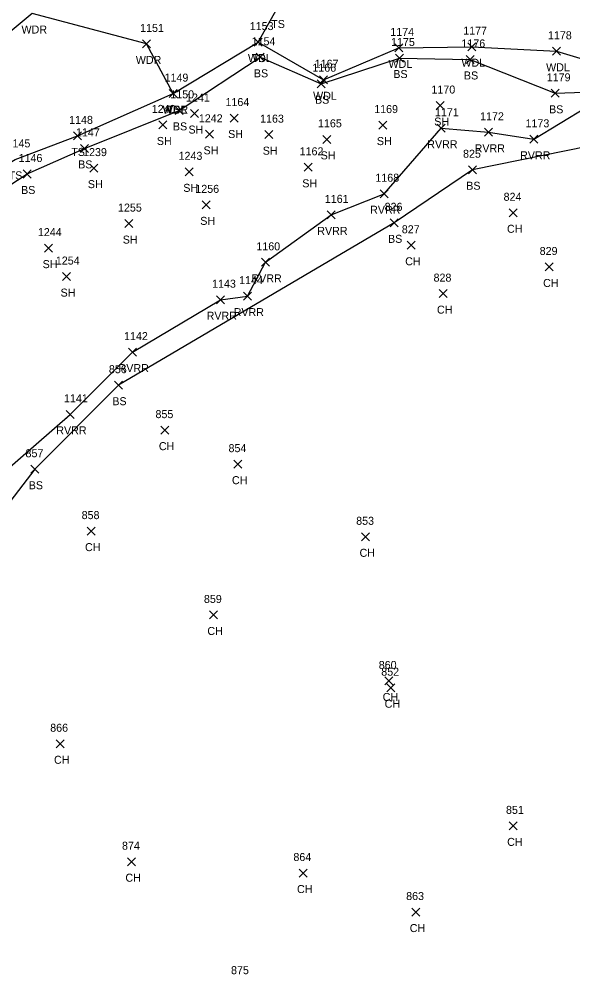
# Model space of a CAD drawing. Extents: x 1885914 to 1887218, y 756253 to 760620.
# Drawn here: x 1886700.7 to 1886839.1, y 759954.5 to 760195 of the extents above; entities that cross this region are included whole.
import ezdxf

# ---------------------------------------------------------------- set-up
doc = ezdxf.new("R2010")
doc.units = 0
for name, color, linetype in [('L_A', 7, 'Continuous'), ('L_I', 7, 'Continuous'), ('L_TIC', 7, 'Continuous'), ('LAWA', 7, 'Continuous'), ('LAWE', 7, 'Continuous'), ('LELB', 7, 'Continuous')]:
    doc.layers.add(name, color=color, linetype=linetype)

msp = doc.modelspace()

# ---------------------------------------------------------------- linework, layer by layer
at = {"layer": 'L_TIC'}
for points in [[(1886759.47, 760188.26), (1886761.47, 760190.26)], [(1886761.47, 760188.26), (1886759.47, 760190.26)], [(1886759.47, 760188.26), (1886761.47, 760190.26)], [(1886761.47, 760188.26), (1886759.47, 760190.26)], [(1886731.49, 760187.8), (1886733.49, 760189.8)], [(1886733.49, 760187.8), (1886731.49, 760189.8)], [(1886794.61, 760186.81), (1886796.61, 760188.81)], [(1886796.61, 760186.81), (1886794.61, 760188.81)], [(1886812.83, 760187.11), (1886814.83, 760189.11)], [(1886814.83, 760187.11), (1886812.83, 760189.11)], [(1886834.01, 760185.96), (1886836.01, 760187.96)], [(1886836.01, 760185.96), (1886834.01, 760187.96)], [(1886759.93, 760184.46), (1886761.93, 760186.46)], [(1886761.93, 760184.46), (1886759.93, 760186.46)], [(1886794.79, 760184.28), (1886796.79, 760186.28)], [(1886796.79, 760184.28), (1886794.79, 760186.28)], [(1886812.44, 760183.92), (1886814.44, 760185.92)], [(1886814.44, 760183.92), (1886812.44, 760185.92)], [(1886775.75, 760178.85), (1886777.75, 760180.85)], [(1886777.75, 760178.85), (1886775.75, 760180.85)], [(1886775.22, 760177.86), (1886777.22, 760179.86)], [(1886777.22, 760177.86), (1886775.22, 760179.86)], [(1886738.18, 760175.38), (1886740.18, 760177.38)], [(1886740.18, 760175.38), (1886738.18, 760177.38)], [(1886738.18, 760175.38), (1886740.18, 760177.38)], [(1886740.18, 760175.38), (1886738.18, 760177.38)], [(1886738.18, 760175.38), (1886740.18, 760177.38)], [(1886740.18, 760175.38), (1886738.18, 760177.38)], [(1886833.73, 760175.46), (1886835.73, 760177.46)], [(1886835.73, 760175.46), (1886833.73, 760177.46)], [(1886804.97, 760172.4), (1886806.97, 760174.4)], [(1886806.97, 760172.4), (1886804.97, 760174.4)], [(1886739.68, 760171.2), (1886741.68, 760173.2)], [(1886741.68, 760171.2), (1886739.68, 760173.2)], [(1886743.53, 760170.4), (1886745.53, 760172.4)], [(1886745.53, 760170.4), (1886743.53, 760172.4)], [(1886753.45, 760169.28), (1886755.45, 760171.28)], [(1886755.45, 760169.28), (1886753.45, 760171.28)], [(1886735.62, 760167.56), (1886737.62, 760169.56)], [(1886737.62, 760167.56), (1886735.62, 760169.56)], [(1886790.63, 760167.52), (1886792.63, 760169.52)], [(1886792.63, 760167.52), (1886790.63, 760169.52)], [(1886805.2, 760166.73), (1886807.2, 760168.73)], [(1886807.2, 760166.73), (1886805.2, 760168.73)], [(1886714.31, 760164.82), (1886716.31, 760166.82)], [(1886716.31, 760164.82), (1886714.31, 760166.82)], [(1886747.3, 760165.22), (1886749.3, 760167.22)], [(1886749.3, 760165.22), (1886747.3, 760167.22)], [(1886762.1, 760165.13), (1886764.1, 760167.13)], [(1886764.1, 760165.13), (1886762.1, 760167.13)], [(1886817.04, 760165.72), (1886819.04, 760167.72)], [(1886819.04, 760165.72), (1886817.04, 760167.72)], [(1886776.57, 760163.96), (1886778.57, 760165.96)], [(1886778.57, 760163.96), (1886776.57, 760165.96)], [(1886828.4, 760163.97), (1886830.4, 760165.97)], [(1886830.4, 760163.97), (1886828.4, 760165.97)], [(1886716, 760161.7), (1886718, 760163.7)], [(1886718, 760161.7), (1886716, 760163.7)], [(1886771.98, 760156.97), (1886773.98, 760158.97)], [(1886773.98, 760156.97), (1886771.98, 760158.97)], [(1886701.73, 760155.3), (1886703.73, 760157.3)], [(1886703.73, 760155.3), (1886701.73, 760157.3)], [(1886718.37, 760156.77), (1886720.37, 760158.77)], [(1886720.37, 760156.77), (1886718.37, 760158.77)], [(1886742.23, 760155.84), (1886744.23, 760157.84)], [(1886744.23, 760155.84), (1886742.23, 760157.84)], [(1886813.02, 760156.37), (1886815.02, 760158.37)], [(1886815.02, 760156.37), (1886813.02, 760158.37)], [(1886790.91, 760150.37), (1886792.91, 760152.37)], [(1886792.91, 760150.37), (1886790.91, 760152.37)], [(1886746.48, 760147.59), (1886748.48, 760149.59)], [(1886748.48, 760147.59), (1886746.48, 760149.59)], [(1886777.71, 760145.09), (1886779.71, 760147.09)], [(1886779.71, 760145.09), (1886777.71, 760147.09)], [(1886823.16, 760145.61), (1886825.16, 760147.61)], [(1886825.16, 760145.61), (1886823.16, 760147.61)], [(1886727.09, 760142.91), (1886729.09, 760144.91)], [(1886729.09, 760142.91), (1886727.09, 760144.91)], [(1886793.47, 760143.1), (1886795.47, 760145.1)], [(1886795.47, 760143.1), (1886793.47, 760145.1)], [(1886707.06, 760136.78), (1886709.06, 760138.78)], [(1886709.06, 760136.78), (1886707.06, 760138.78)], [(1886797.71, 760137.49), (1886799.71, 760139.49)], [(1886799.71, 760137.49), (1886797.71, 760139.49)], [(1886761.25, 760133.23), (1886763.25, 760135.23)], [(1886763.25, 760133.23), (1886761.25, 760135.23)], [(1886832.19, 760132.07), (1886834.19, 760134.07)], [(1886834.19, 760132.07), (1886832.19, 760134.07)], [(1886711.56, 760129.67), (1886713.56, 760131.67)], [(1886713.56, 760129.67), (1886711.56, 760131.67)], [(1886750.04, 760123.89), (1886752.04, 760125.89)], [(1886752.04, 760123.89), (1886750.04, 760125.89)], [(1886756.81, 760124.78), (1886758.81, 760126.78)], [(1886758.81, 760124.78), (1886756.81, 760126.78)], [(1886805.66, 760125.41), (1886807.66, 760127.41)], [(1886807.66, 760125.41), (1886805.66, 760127.41)], [(1886728.03, 760110.8), (1886730.03, 760112.8)], [(1886730.03, 760110.8), (1886728.03, 760112.8)], [(1886724.54, 760102.53), (1886726.54, 760104.53)], [(1886726.54, 760102.53), (1886724.54, 760104.53)], [(1886712.46, 760095.25), (1886714.46, 760097.25)], [(1886714.46, 760095.25), (1886712.46, 760097.25)], [(1886736.13, 760091.3), (1886738.13, 760093.3)], [(1886738.13, 760091.3), (1886736.13, 760093.3)], [(1886754.39, 760082.8), (1886756.39, 760084.8)], [(1886756.39, 760082.8), (1886754.39, 760084.8)], [(1886703.64, 760081.53), (1886705.64, 760083.53)], [(1886705.64, 760081.53), (1886703.64, 760083.53)], [(1886717.67, 760066.07), (1886719.67, 760068.07)], [(1886719.67, 760066.07), (1886717.67, 760068.07)], [(1886786.31, 760064.65), (1886788.31, 760066.65)], [(1886788.31, 760064.65), (1886786.31, 760066.65)], [(1886748.25, 760045.12), (1886750.25, 760047.12)], [(1886750.25, 760045.12), (1886748.25, 760047.12)], [(1886792.08, 760028.63), (1886794.08, 760030.63)], [(1886794.08, 760028.63), (1886792.08, 760030.63)], [(1886792.57, 760026.94), (1886794.57, 760028.94)], [(1886794.57, 760026.94), (1886792.57, 760028.94)], [(1886709.91, 760012.94), (1886711.91, 760014.94)], [(1886711.91, 760012.94), (1886709.91, 760014.94)], [(1886823.2, 759992.42), (1886825.2, 759994.42)], [(1886825.2, 759992.42), (1886823.2, 759994.42)], [(1886727.76, 759983.47), (1886729.76, 759985.47)], [(1886729.76, 759983.47), (1886727.76, 759985.47)], [(1886770.66, 759980.64), (1886772.66, 759982.64)], [(1886772.66, 759980.64), (1886770.66, 759982.64)], [(1886798.85, 759970.89), (1886800.85, 759972.89)], [(1886800.85, 759970.89), (1886798.85, 759972.89)]]:
    msp.add_lwpolyline(points, dxfattribs=at)
at = {"layer": 'LAWA'}
for points in [[(1886739.18, 760176.38), (1886732.49, 760188.8), (1886703.91, 760196.4), (1886681.18, 760177.48), (1886662.74, 760171.57), (1886662.99, 760182.72), (1886681.62, 760215.3), (1886695.77, 760245.06), (1886708.75, 760275.76), (1886734.57, 760330.32)], [(1886739.18, 760176.38), (1886760.47, 760189.26), (1886776.75, 760179.85), (1886795.61, 760187.81), (1886813.83, 760188.11), (1886835.01, 760186.96), (1886850.86, 760182.23), (1886861.69, 760175.78)]]:
    msp.add_lwpolyline(points, dxfattribs=at)
at = {"layer": 'LAWE'}
msp.add_lwpolyline([(1886643.57, 759950.66), (1886647.93, 759967.68), (1886650.25, 759980.54), (1886657.27, 760004.64), (1886666.09, 760031.44), (1886675.36, 760057.62), (1886682.23, 760063.3), (1886696.4, 760081.41), (1886713.46, 760096.25), (1886729.03, 760111.8), (1886751.04, 760124.89), (1886757.81, 760125.78), (1886762.25, 760134.23), (1886778.71, 760146.09), (1886791.91, 760151.37), (1886806.2, 760167.73), (1886818.04, 760166.72), (1886829.4, 760164.97), (1886849.11, 760176.99)], dxfattribs=at)
at = {"layer": 'LELB'}
for points in [[(1886760.47, 760189.26), (1886765.29, 760197.79), (1886777.79, 760220.1), (1886797.3, 760246.72), (1886812.15, 760261.2), (1886826.33, 760277.53)], [(1887191.67, 760127.4), (1887162.59, 760142.97), (1887139.96, 760151.52), (1887098.78, 760169.34), (1887064.77, 760179.63), (1887039.44, 760184.45), (1887015.43, 760186.04), (1886988.17, 760195.78), (1886958.13, 760192.47), (1886941.93, 760196.3), (1886915.34, 760186.03), (1886875.72, 760169.95), (1886843.17, 760163.26), (1886814.02, 760157.37), (1886794.47, 760144.1), (1886725.54, 760103.53), (1886704.64, 760082.53), (1886687.39, 760060.16), (1886675.38, 760043.91), (1886662.89, 760014.32), (1886651.59, 759963.58), (1886647.85, 759929.2)], [(1886569.47, 759932.79), (1886578.55, 759960.06), (1886589.25, 759986.28), (1886598.57, 760012.52), (1886604.77, 760034.06), (1886609.07, 760058.69), (1886625.15, 760085.1), (1886640.42, 760091.38), (1886649.45, 760109.89), (1886661.77, 760128.12), (1886683.78, 760144.02), (1886702.73, 760156.3), (1886717, 760162.7), (1886740.68, 760172.2), (1886760.93, 760185.46), (1886776.22, 760178.86), (1886795.79, 760185.28), (1886813.44, 760184.92), (1886834.73, 760176.46), (1886849.11, 760176.99)], [(1886572.3, 759803.95), (1886568.6, 759823.21), (1886564.73, 759854.7), (1886563.87, 759883.9), (1886566.65, 759905.78), (1886566.1, 759932.48), (1886575.22, 759961.15), (1886584.71, 759987.76), (1886595.18, 760013.31), (1886601.19, 760034.22), (1886605.14, 760059.41), (1886622.97, 760086.15), (1886635.93, 760094.98), (1886646.75, 760112.81), (1886658.85, 760130.9), (1886680.3, 760148.52), (1886699.66, 760159.95), (1886715.31, 760165.82), (1886739.18, 760176.38)]]:
    msp.add_lwpolyline(points, dxfattribs=at)

# ---------------------------------------------------------------- texts
at = {"layer": 'L_A'}
for s, p in [('WDR', (1886701.27, 760191.4)), ('TS', (1886763.7, 760192.79)), ('WDR', (1886729.85, 760183.8)), ('WDL', (1886757.89, 760184.26)), ('TS', (1886758.88, 760184.26)), ('WDL', (1886793.03, 760182.81)), ('WDL', (1886811.25, 760183.11)), ('WDL', (1886832.43, 760181.96)), ('BS', (1886759.37, 760180.46)), ('BS', (1886794.23, 760180.28)), ('BS', (1886811.88, 760179.92)), ('WDL', (1886774.17, 760174.85)), ('BS', (1886774.66, 760173.86)), ('WDR', (1886736.54, 760171.38)), ('WDL', (1886736.6, 760171.38)), ('TS', (1886737.59, 760171.38)), ('BS', (1886833.17, 760171.46)), ('BS', (1886739.12, 760167.2)), ('SH', (1886804.46, 760168.4)), ('SH', (1886743.02, 760166.4)), ('SH', (1886752.94, 760165.28)), ('SH', (1886735.11, 760163.56)), ('SH', (1886790.12, 760163.52)), ('RVRR', (1886802.71, 760162.73)), ('RVRR', (1886814.56, 760161.72)), ('TS', (1886713.72, 760160.82)), ('SH', (1886746.79, 760161.22)), ('SH', (1886761.59, 760161.13)), ('SH', (1886776.06, 760159.96)), ('RVRR', (1886825.92, 760159.97)), ('BS', (1886715.44, 760157.7)), ('TS', (1886698.07, 760154.95)), ('SH', (1886717.86, 760152.77)), ('SH', (1886771.47, 760152.97)), ('BS', (1886812.46, 760152.37)), ('BS', (1886701.17, 760151.3)), ('SH', (1886741.72, 760151.84)), ('RVRR', (1886788.43, 760146.37)), ('SH', (1886745.96, 760143.59)), ('RVRR', (1886775.22, 760141.09)), ('CH', (1886822.65, 760141.61)), ('SH', (1886726.58, 760138.91)), ('BS', (1886792.91, 760139.1)), ('CH', (1886797.2, 760133.49)), ('SH', (1886706.55, 760132.78)), ('RVRR', (1886758.76, 760129.23)), ('CH', (1886831.68, 760128.07)), ('SH', (1886711.04, 760125.67)), ('CH', (1886805.14, 760121.41)), ('RVRR', (1886747.56, 760119.89)), ('RVRR', (1886754.32, 760120.78)), ('RVRR', (1886725.54, 760106.8)), ('BS', (1886723.98, 760098.53)), ('RVRR', (1886709.97, 760091.25)), ('CH', (1886735.62, 760087.3)), ('BS', (1886703.08, 760077.53)), ('CH', (1886753.88, 760078.8)), ('CH', (1886717.16, 760062.07)), ('CH', (1886785.79, 760060.65)), ('CH', (1886747.74, 760041.12)), ('CH', (1886791.57, 760024.63)), ('CH', (1886792.06, 760022.94)), ('CH', (1886709.4, 760008.94)), ('CH', (1886822.69, 759988.42)), ('CH', (1886727.25, 759979.47)), ('CH', (1886770.15, 759976.64)), ('CH', (1886798.34, 759966.89))]:
    msp.add_text(s, height=2, dxfattribs=at).set_placement(p)
at = {"layer": 'L_I'}
for s, p in [('1151', (1886730.93, 760191.8)), ('1153', (1886758.34, 760192.26)), ('1153', (1886758.34, 760192.26)), ('1174', (1886793.48, 760190.81)), ('1177', (1886811.71, 760191.11)), ('1154', (1886758.8, 760188.46)), ('1175', (1886793.66, 760188.28)), ('1178', (1886832.89, 760189.96)), ('1176', (1886811.26, 760187.92)), ('1166', (1886773.99, 760181.86)), ('1167', (1886774.58, 760182.85)), ('1149', (1886737.04, 760179.38)), ('1149', (1886737.04, 760179.38)), ('1149', (1886737.04, 760179.38)), ('1179', (1886832.59, 760179.46)), ('1170', (1886803.76, 760176.4)), ('1150', (1886738.47, 760175.2)), ('1241', (1886742.4, 760174.4)), ('1240', (1886733.84, 760171.56)), ('1164', (1886752.27, 760173.28)), ('1169', (1886789.45, 760171.52)), ('1242', (1886745.61, 760169.22)), ('1163', (1886760.92, 760169.13)), ('1171', (1886804.64, 760170.73)), ('1172', (1886815.92, 760169.72)), ('1148', (1886713.18, 760168.82)), ('1165', (1886775.4, 760167.96)), ('1173', (1886827.28, 760167.97)), ('1147', (1886714.88, 760165.7)), ('1145', (1886697.54, 760162.95)), ('1146', (1886700.55, 760159.3)), ('1239', (1886716.67, 760160.77)), ('1243', (1886740.54, 760159.84)), ('1162', (1886770.81, 760160.97)), ('825', (1886811.66, 760160.37)), ('1168', (1886789.74, 760154.37)), ('1256', (1886744.73, 760151.59)), ('1161', (1886777.1, 760149.09)), ('824', (1886821.8, 760149.61)), ('1255', (1886725.4, 760146.91)), ('826', (1886792.06, 760147.1)), ('1244', (1886705.37, 760140.78)), ('827', (1886796.35, 760141.49)), ('1160', (1886759.99, 760137.23)), ('829', (1886830.82, 760136.07)), ('1254', (1886709.86, 760133.67)), ('1144', (1886755.68, 760128.78)), ('828', (1886804.29, 760129.41)), ('1143', (1886748.92, 760127.89)), ('1142', (1886726.91, 760114.8)), ('856', (1886723.12, 760106.53)), ('1141', (1886711.9, 760099.25)), ('855', (1886734.77, 760095.3)), ('857', (1886702.28, 760085.53)), ('854', (1886753.03, 760086.8)), ('858', (1886716.31, 760070.07)), ('853', (1886784.94, 760068.65)), ('859', (1886746.88, 760049.12)), ('860', (1886790.59, 760032.63)), ('852', (1886791.21, 760030.94)), ('866', (1886708.45, 760016.94)), ('851', (1886822.4, 759996.42)), ('874', (1886726.4, 759987.47)), ('864', (1886769.25, 759984.64)), ('863', (1886797.44, 759974.89)), ('875', (1886753.66, 759956.37))]:
    msp.add_text(s, height=2, dxfattribs=at).set_placement(p)

doc.saveas('drawing.dxf')
